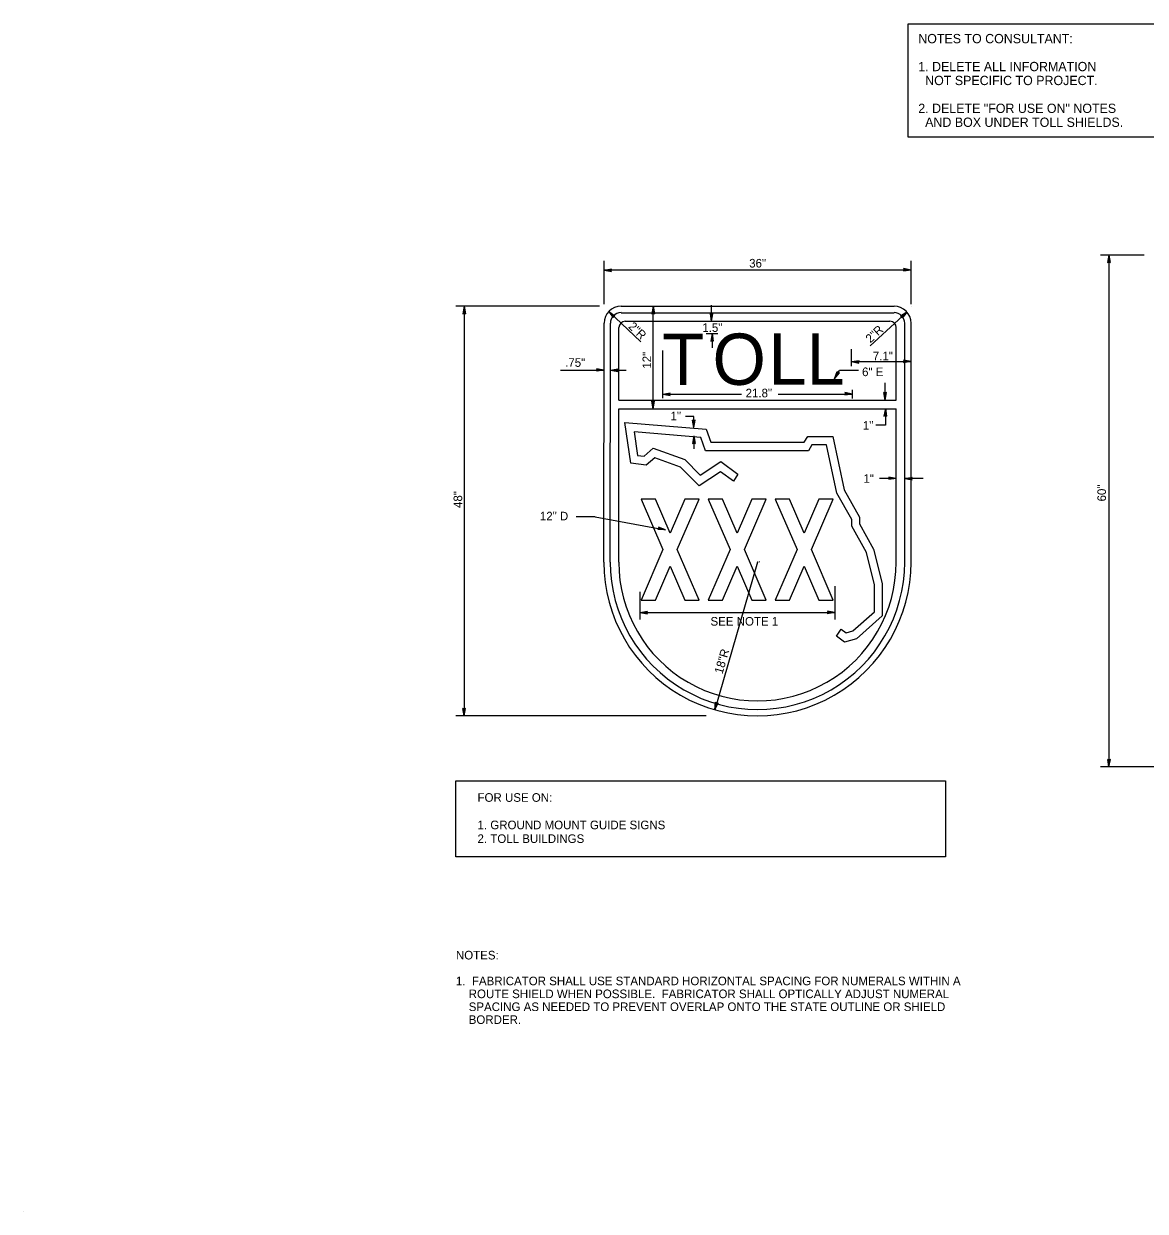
# Model space of a CAD drawing. Extents: x 52194 to 54069, y 8993 to 10153.
# Drawn here: x 52194 to 53290, y 8993 to 10153 of the extents above; entities that cross this region are included whole.
import ezdxf

# ---------------------------------------------------------------- set-up
doc = ezdxf.new("R2010")
doc.units = 0
for name, color, linetype in [('AdhocPoint_dp', 7, 'Continuous'), ('GSDims', 7, 'Continuous'), ('SignPanel', 7, 'Continuous'), ('TextAlert', 7, 'Continuous'), ('TextLabel', 7, 'Continuous'), ('TextNotes', 7, 'Continuous')]:
    doc.layers.add(name, color=color, linetype=linetype)

msp = doc.modelspace()

# ---------------------------------------------------------------- linework, layer by layer
at = {"layer": 'AdhocPoint_dp'}
msp.add_line((52193.9, 8993), (52193.9, 8993), dxfattribs=at)
at = {"layer": 'GSDims'}
for p, q in [((52760.8, 9879), (52760.8, 9921.6)), ((53060.8, 9879), (53060.8, 9921.6)), ((53288.6, 9927), (53246, 9927)), ((53254.1, 9927), (53252.7, 9919.8)), ((53252.7, 9919.8), (53254, 9920.3)), ((53254.1, 9927), (53253.3, 9920)), ((53254, 9920.3), (53255.2, 9919.7)), ((53254.1, 9927), (53255.2, 9919.7)), ((53254.1, 9927), (53254.6, 9920)), ((53254.1, 9927), (53254.1, 9427)), ((52760.8, 9912.4), (52768.1, 9913.5)), ((52760.8, 9912.4), (52767.8, 9912.9)), ((52760.8, 9912.4), (52768.1, 9911)), ((52760.8, 9912.4), (52767.8, 9911.6)), ((53060.8, 9912.4), (52760.8, 9912.4)), ((52767.6, 9912.3), (52768.1, 9913.5)), ((52768.1, 9911), (52767.6, 9912.3)), ((53060.8, 9912.4), (53053.5, 9913.8)), ((53053.5, 9913.8), (53054, 9912.5)), ((53054, 9912.5), (53053.5, 9911.2)), ((53060.8, 9912.4), (53053.5, 9911.2)), ((53060.8, 9912.4), (53053.8, 9913.1)), ((53060.8, 9912.4), (53053.8, 9911.9)), ((52756.4, 9877), (52616.1, 9877)), ((52624.2, 9877), (52622.8, 9869.7)), ((52624.2, 9877), (52623.4, 9870)), ((52624.2, 9877), (52625.3, 9869.7)), ((52624.2, 9877), (52624.7, 9870)), ((52624.2, 9877), (52624.2, 9477)), ((52660.7, 9877), (52660.7, 9877)), ((52765.4, 9871.9), (52796.7, 9842.4)), ((52765.4, 9871.9), (52771.5, 9867.7)), ((52765.4, 9871.9), (52769.7, 9865.9)), ((52765.4, 9871.9), (52770, 9866.6)), ((52765.4, 9871.9), (52770.9, 9867.4)), ((52808.8, 9877), (52807.4, 9869.7)), ((52808.8, 9877), (52808.1, 9870)), ((52808.8, 9877), (52810, 9869.7)), ((52808.8, 9877), (52809.3, 9870)), ((52808.8, 9777), (52808.8, 9877)), ((52865.8, 9862.4), (52865.8, 9878.1)), ((53060.8, 9877), (53060.8, 9877)), ((52622.8, 9869.7), (52624.1, 9870.2)), ((52624.1, 9870.2), (52625.3, 9869.7)), ((52769.7, 9865.9), (52770.2, 9867.2)), ((52770.2, 9867.2), (52771.5, 9867.7)), ((52807.4, 9869.7), (52808.7, 9870.3)), ((52808.7, 9870.3), (52810, 9869.7)), ((52865.8, 9862.4), (52864.7, 9869.7)), ((52865.9, 9869.2), (52864.7, 9869.7)), ((52865.8, 9862.4), (52865.3, 9869.4)), ((52865.8, 9862.4), (52867.2, 9869.7)), ((52865.8, 9862.4), (52866.6, 9869.4)), ((52867.2, 9869.7), (52865.9, 9869.2)), ((53056.7, 9871.3), (53020.9, 9838.3)), ((53056.7, 9871.3), (53050.4, 9867.4)), ((53050.4, 9867.4), (53051.6, 9866.8)), ((53056.7, 9871.3), (53051, 9867.1)), ((53051.6, 9866.8), (53052.1, 9865.5)), ((53056.7, 9871.3), (53051.9, 9866.2)), ((53056.7, 9871.3), (53052.1, 9865.5)), ((52860.7, 9850.4), (52872.1, 9850.4)), ((52866.4, 9850.4), (52865, 9843.1)), ((52866.4, 9850.4), (52865.6, 9843.4)), ((52866.4, 9850.4), (52866.4, 9836.4)), ((52866.4, 9850.4), (52867.5, 9843.1)), ((52866.4, 9850.4), (52866.9, 9843.4)), ((52865, 9843.1), (52866.3, 9843.6)), ((52866.3, 9843.6), (52867.5, 9843.1)), ((53026.4, 9842.4), (53026.4, 9842.4)), ((52818.1, 9787.2), (52818.1, 9834)), ((53002.6, 9818.5), (53002.6, 9835)), ((52718.4, 9814.7), (52760.8, 9814.7)), ((52760.8, 9814.7), (52753.5, 9816.1)), ((52753.5, 9816.1), (52754, 9814.8)), ((52754, 9814.8), (52753.5, 9813.6)), ((52760.8, 9814.7), (52753.5, 9813.6)), ((52760.8, 9814.7), (52753.8, 9815.5)), ((52760.8, 9814.7), (52753.8, 9814.2)), ((52767, 9814.7), (52774.3, 9815.9)), ((52767, 9814.7), (52774, 9815.2)), ((52767, 9814.7), (52774.2, 9813.3)), ((52767, 9814.7), (52774, 9814)), ((52767, 9814.7), (52782.3, 9814.7)), ((52773.7, 9814.6), (52774.3, 9815.9)), ((52774.2, 9813.3), (52773.7, 9814.6)), ((52986, 9806.3), (52990.7, 9814.4)), ((53009.4, 9814.4), (52990.7, 9814.4)), ((53002.6, 9823), (53009.9, 9824.2)), ((53002.6, 9823), (53009.6, 9823.5)), ((53002.6, 9823), (53060.8, 9823)), ((53002.6, 9823), (53009.8, 9821.6)), ((53002.6, 9823), (53009.6, 9822.3)), ((53009.3, 9822.9), (53009.9, 9824.2)), ((53009.8, 9821.6), (53009.3, 9822.9)), ((53060.8, 9823), (53053.5, 9824.4)), ((53053.5, 9824.4), (53054, 9823.1)), ((53054, 9823.1), (53053.5, 9821.9)), ((53060.8, 9823), (53053.5, 9821.9)), ((53060.8, 9823), (53053.8, 9823.8)), ((53060.8, 9823), (53053.8, 9822.5)), ((52986, 9806.3), (52988.6, 9813.2)), ((52986, 9806.3), (52989.1, 9812.6)), ((52986, 9806.3), (52990.1, 9812)), ((52986, 9806.3), (52990.9, 9811.9)), ((52989.5, 9812.1), (52988.6, 9813.2)), ((52990.9, 9811.9), (52989.5, 9812.1)), ((53035.6, 9785.4), (53035.4, 9802.3)), ((52818.1, 9791.3), (52825.4, 9792.5)), ((52818.1, 9791.3), (52825.1, 9791.8)), ((52818.1, 9791.3), (52825.4, 9789.9)), ((52818.1, 9791.3), (52825.1, 9790.6)), ((52818.1, 9791.3), (52895.2, 9791.3)), ((52824.8, 9791.2), (52825.4, 9792.5)), ((52825.4, 9789.9), (52824.8, 9791.2)), ((52931, 9791.3), (53003.5, 9791.3)), ((53003.5, 9791.3), (52996.2, 9792.7)), ((52996.2, 9792.7), (52996.8, 9791.4)), ((52996.8, 9791.4), (52996.2, 9790.1)), ((53003.5, 9791.3), (52996.2, 9790.1)), ((53003.5, 9791.3), (52996.5, 9792)), ((53003.5, 9791.3), (52996.5, 9790.8)), ((53003.5, 9787), (53003.5, 9795.5)), ((53035.6, 9785.4), (53034.3, 9792.7)), ((53035.6, 9792.1), (53034.3, 9792.7)), ((53035.6, 9785.4), (53035, 9792.4)), ((53035.6, 9785.4), (53036.9, 9792.7)), ((53036.9, 9792.7), (53035.6, 9792.1)), ((53035.6, 9785.4), (53036.2, 9792.4)), ((52808.8, 9777), (52807.6, 9784.3)), ((52808.9, 9783.7), (52807.6, 9784.3)), ((52808.8, 9777), (52808.3, 9784)), ((52808.8, 9777), (52810.2, 9784.3)), ((52808.8, 9777), (52809.5, 9784)), ((52810.2, 9784.3), (52808.9, 9783.7)), ((52848.4, 9769.3), (52840.5, 9769.3)), ((52848.4, 9758.6), (52848.4, 9769.3)), ((53035.7, 9777.1), (53034.3, 9769.8)), ((53034.3, 9769.8), (53035.6, 9770.3)), ((53035.7, 9777.1), (53035, 9770.1)), ((53035.6, 9770.3), (53036.9, 9769.8)), ((53035.7, 9777.1), (53035.9, 9761)), ((53035.7, 9777.1), (53036.9, 9769.8)), ((53035.7, 9777.1), (53036.2, 9770.1)), ((52848.4, 9758.6), (52847.2, 9765.9)), ((52848.5, 9765.3), (52847.2, 9765.9)), ((52848.4, 9758.6), (52847.9, 9765.6)), ((52848.4, 9758.6), (52849.8, 9765.9)), ((52848.4, 9758.6), (52849.1, 9765.6)), ((52849.8, 9765.9), (52848.5, 9765.3)), ((53035.9, 9761), (53026.2, 9761)), ((52848.4, 9750.4), (52847.1, 9743.1)), ((52848.4, 9750.4), (52847.8, 9743.4)), ((52848.4, 9750.4), (52848.6, 9737.9)), ((52848.4, 9750.4), (52849.7, 9743.1)), ((52848.4, 9750.4), (52849, 9743.4)), ((52847.1, 9743.1), (52848.4, 9743.7)), ((52848.4, 9743.7), (52849.7, 9743.1)), ((53046.3, 9708.8), (53039, 9710.2)), ((53039, 9710.2), (53039.5, 9708.9)), ((53046.3, 9708.8), (53039.3, 9709.6)), ((53054.6, 9708.8), (53061.9, 9710)), ((53054.6, 9708.8), (53061.6, 9709.3)), ((53061.3, 9708.7), (53061.9, 9710)), ((53046.3, 9708.8), (53029.8, 9708.8)), ((53039.5, 9708.9), (53039, 9707.7)), ((53046.3, 9708.8), (53039, 9707.7)), ((53046.3, 9708.8), (53039.3, 9708.3)), ((53054.6, 9708.8), (53061.8, 9707.4)), ((53054.6, 9708.8), (53061.6, 9708.1)), ((53072.5, 9708.8), (53054.6, 9708.8)), ((53061.8, 9707.4), (53061.3, 9708.7)), ((52752.1, 9671.4), (52733.7, 9671.4)), ((52752.1, 9671.4), (52820.9, 9658.7)), ((52814.3, 9660.1), (52813.5, 9658.9)), ((52820.9, 9658.7), (52813.5, 9658.9)), ((52820.9, 9658.7), (52814, 9661.4)), ((52814, 9661.4), (52814.3, 9660.1)), ((52820.9, 9658.7), (52814, 9659.5)), ((52820.9, 9658.7), (52814.2, 9660.7)), ((52910.8, 9627), (52869.2, 9482.9)), ((52910.8, 9627), (52910.8, 9627)), ((52910.8, 9627), (52910.8, 9627)), ((52795.9, 9598), (52795.9, 9571)), ((52986.3, 9603.8), (52986.3, 9571)), ((52795.9, 9577.9), (52803.2, 9579.1)), ((52795.9, 9577.9), (52802.9, 9578.4)), ((52795.9, 9577.9), (52803.2, 9576.5)), ((52795.9, 9577.9), (52802.9, 9577.2)), ((52795.9, 9577.9), (52875.5, 9577.9)), ((52802.6, 9577.8), (52803.2, 9579.1)), ((52803.2, 9576.5), (52802.6, 9577.8)), ((52875.5, 9577.9), (52986.3, 9577.9)), ((52986.3, 9577.9), (52979, 9579.3)), ((52979, 9579.3), (52979.6, 9578)), ((52979.6, 9578), (52979, 9576.7)), ((52986.3, 9577.9), (52979, 9576.7)), ((52986.3, 9577.9), (52979.3, 9578.6)), ((52986.3, 9577.9), (52979.3, 9577.4)), ((52869.2, 9482.9), (52869.8, 9490.3)), ((52869.2, 9482.9), (52870.4, 9489.9)), ((52869.2, 9482.9), (52872.3, 9489.6)), ((52869.2, 9482.9), (52871.6, 9489.5)), ((52869.8, 9490.3), (52871, 9489.4)), ((52871, 9489.4), (52872.3, 9489.6)), ((52624.2, 9477), (52623, 9484.3)), ((52624.3, 9483.7), (52623, 9484.3)), ((52624.2, 9477), (52623.7, 9484)), ((52624.2, 9477), (52625.6, 9484.3)), ((52624.2, 9477), (52624.9, 9484)), ((52625.6, 9484.3), (52624.3, 9483.7)), ((52860.6, 9477), (52616.1, 9477)), ((53254.1, 9427), (53252.9, 9434.3)), ((53254.2, 9433.8), (53252.9, 9434.3)), ((53254.1, 9427), (53253.6, 9434)), ((53254.1, 9427), (53255.5, 9434.3)), ((53254.1, 9427), (53254.8, 9434)), ((53255.5, 9434.3), (53254.2, 9433.8)), ((53490.5, 9427), (53246, 9427))]:
    msp.add_line(p, q, dxfattribs=at)
for radius in [0.141, 0.141, 0.0707]:
    msp.add_circle((52910.8, 9627.1), radius, dxfattribs=at)
at = {"layer": 'SignPanel'}
for p, q in [((52777.4, 9877), (53044.1, 9877)), ((52760.7, 9627.1), (52760.8, 9860.4)), ((52766.9, 9627.1), (52767, 9860.4)), ((52777.4, 9870.7), (53044.1, 9870.7)), ((52781.5, 9862.4), (53040.1, 9862.4)), ((53054.6, 9627), (53054.6, 9860.4)), ((53060.8, 9627), (53060.8, 9860.4)), ((52775.3, 9785.3), (52775.3, 9856.2)), ((53046.3, 9785.3), (53046.3, 9856.2)), ((52775.3, 9785.3), (53046.3, 9785.3)), ((52775.3, 9627), (52775.3, 9777)), ((52775.3, 9777), (53046.3, 9777)), ((53046.3, 9627), (53046.3, 9777)), ((52781.2, 9763.6), (52860.7, 9756.9)), ((52786.9, 9723.9), (52781.2, 9763.6)), ((52860.7, 9756.9), (52865.2, 9744.4)), ((52855.3, 9749), (52790.3, 9754.4)), ((52790.3, 9754.4), (52793.6, 9731.4)), ((52859.9, 9736), (52855.3, 9749)), ((52865.2, 9744.4), (52956.3, 9744.4)), ((52956.3, 9744.4), (52959.8, 9750)), ((52959.8, 9750), (52984.3, 9750)), ((52984.3, 9750), (52995.4, 9697.7)), ((52799.9, 9730.6), (52808.9, 9738.3)), ((52808.9, 9738.3), (52839.6, 9727.4)), ((52960.4, 9736), (52859.9, 9736)), ((52963.9, 9741.6), (52960.4, 9736)), ((52978.2, 9741.6), (52963.9, 9741.6)), ((52988.2, 9694.5), (52978.2, 9741.6)), ((52802.1, 9721.8), (52786.9, 9723.9)), ((52793.6, 9731.4), (52799.9, 9730.6)), ((52810.4, 9729), (52802.1, 9721.8)), ((52835.6, 9720), (52810.4, 9729)), ((52839.6, 9727.4), (52854.6, 9712.2)), ((52854.6, 9712.2), (52875, 9725.3)), ((52875, 9725.3), (52891.6, 9713)), ((52853.6, 9701.8), (52835.6, 9720)), ((52874.7, 9715.4), (52853.6, 9701.8)), ((52887.3, 9706.1), (52874.7, 9715.4)), ((52891.6, 9713), (52887.3, 9706.1)), ((52995.4, 9697.7), (53010.5, 9671.2)), ((52811.1, 9688.5), (52797.1, 9688.5)), ((52797.1, 9688.5), (52818.4, 9639.3)), ((52825.4, 9655.4), (52811.1, 9688.5)), ((52839.8, 9688.5), (52825.4, 9655.4)), ((52832.4, 9639.3), (52853.8, 9688.5)), ((52853.8, 9688.5), (52839.8, 9688.5)), ((52876.6, 9688.5), (52862.6, 9688.5)), ((52862.6, 9688.5), (52883.9, 9639.3)), ((52890.9, 9655.4), (52876.6, 9688.5)), ((52905.3, 9688.5), (52890.9, 9655.4)), ((52897.9, 9639.3), (52919.3, 9688.5)), ((52919.3, 9688.5), (52905.3, 9688.5)), ((52942.1, 9688.5), (52928.1, 9688.5)), ((52928.1, 9688.5), (52949.4, 9639.3)), ((52956.4, 9655.4), (52942.1, 9688.5)), ((52970.8, 9688.5), (52956.4, 9655.4)), ((52963.4, 9639.3), (52984.8, 9688.5)), ((52984.8, 9688.5), (52970.8, 9688.5)), ((53002.9, 9668.8), (52988.2, 9694.5)), ((53002.9, 9662.1), (53002.9, 9668.8)), ((53010.5, 9671.2), (53010.5, 9664.4)), ((53010.5, 9664.4), (53024.2, 9639.8)), ((53017.1, 9636.5), (53002.9, 9662.1)), ((53024.2, 9639.8), (53032.6, 9606.1)), ((52818.4, 9639.3), (52797.1, 9590.1)), ((52853.8, 9590.1), (52832.4, 9639.3)), ((52883.9, 9639.3), (52862.6, 9590.1)), ((52919.3, 9590.1), (52897.9, 9639.3)), ((52949.4, 9639.3), (52928.1, 9590.1)), ((52984.8, 9590.1), (52963.4, 9639.3)), ((53025, 9605), (53017.1, 9636.5)), ((52811.1, 9590.1), (52825.4, 9623.2)), ((52825.4, 9623.2), (52839.8, 9590.1)), ((52876.6, 9590.1), (52890.9, 9623.2)), ((52890.9, 9623.2), (52905.3, 9590.1)), ((52942.1, 9590.1), (52956.4, 9623.2)), ((52956.4, 9623.2), (52970.8, 9590.1)), ((53025, 9578.6), (53025, 9605)), ((53032.6, 9606.1), (53032.6, 9574.7)), ((52797.1, 9590.1), (52811.1, 9590.1)), ((52839.8, 9590.1), (52853.8, 9590.1)), ((52862.6, 9590.1), (52876.6, 9590.1)), ((52905.3, 9590.1), (52919.3, 9590.1)), ((52928.1, 9590.1), (52942.1, 9590.1)), ((52970.8, 9590.1), (52984.8, 9590.1)), ((53004, 9559.9), (53025, 9578.6)), ((53032.6, 9574.7), (53007.5, 9552.1)), ((52988, 9554.8), (52992.4, 9561.6)), ((52992.4, 9561.6), (52997.2, 9558.1)), ((52997.2, 9558.1), (53004, 9559.9)), ((52995.6, 9549), (52988, 9554.8)), ((53007.5, 9552.1), (52995.6, 9549))]:
    msp.add_line(p, q, dxfattribs=at)
for centre, radius, start, end in [((52777.5, 9860.4), 16.7, 90, 179.9763), ((53044.1, 9860.4), 16.7, 0, 90), ((52777.5, 9860.4), 10.5, 90, 179.9763), ((52781.5, 9856.2), 6.2, 90, 180), ((53040.1, 9856.2), 6.2, 0, 90), ((53044.1, 9860.4), 10.5, 0, 90), ((52910.7, 9627.1), 150.1, 179.9809, 359.9809), ((52910.7, 9627.1), 143.9, 179.9809, 359.9809), ((52910.7, 9627.1), 135.5, 179.9809, 359.9809)]:
    msp.add_arc(centre, radius, start, end, dxfattribs=at)
at = {"layer": 'TextAlert'}
msp.add_lwpolyline([(53057.8, 10153), (53309.9, 10153), (53309.9, 10042.3), (53057.8, 10042.3)], close=True, dxfattribs=at)
at = {"layer": 'TextLabel'}
msp.add_lwpolyline([(52616.1, 9413.6), (53094.4, 9413.6), (53094.4, 9339.3), (52616.1, 9339.3)], close=True, dxfattribs=at)

# ---------------------------------------------------------------- texts
at = {"layer": 'GSDims'}
for s, p in [('36"', (52902.6, 9914.9)), ('1.5"', (52856.8, 9852)), ('.75"', (52722.8, 9817.9)), ('7.1"', (53023.4, 9824.3)), ('6" E', (53012.9, 9808.8)), ('21.8"', (52899.1, 9788.1)), ('1"', (52825.8, 9765.7)), ('1"', (53013.7, 9756.5)), ('1"', (53014.2, 9704.6)), ('12" D', (52698.1, 9667.9)), ('SEE NOTE 1', (52864.8, 9565.1))]:
    msp.add_text(s, height=8.4, dxfattribs=at).set_placement(p)
for s, rotation, p in [('2"R', 316.5174, (52783.9, 9856.5)), ('2"R', 42.5752, (53021, 9840.7)), ('12"', 90, (52806.8, 9816.1)), ('60"', 90, (53251.2, 9686.4)), ('48"', 90, (52622.2, 9680)), ('.', 90, (52913.3, 9625.9)), ('18"R', 73.8557, (52876.5, 9517.3))]:
    msp.add_text(s, height=8.4, rotation=rotation, dxfattribs=at).set_placement(p)
at = {"layer": 'SignPanel'}
for s, height, p in [('T', 50.1, (52817.7, 9800.2)), ('O', 50.1, (52866.8, 9800.3)), ('LL', 50.08, (52921.5, 9800.5))]:
    msp.add_text(s, height=height, dxfattribs=at).set_placement(p)
at = {"layer": 'TextAlert'}
for s, p in [('NOTES TO CONSULTANT:', (53067.8, 10134)), ('1. DELETE ALL INFORMATION', (53067.8, 10106.7)), ('  NOT SPECIFIC TO PROJECT.', (53067.8, 10093.1)), ('2. DELETE "FOR USE ON" NOTES', (53067.8, 10065.9)), ('  AND BOX UNDER TOLL SHIELDS.', (53067.8, 10052.3))]:
    msp.add_text(s, height=9.072, dxfattribs=at).set_placement(p)
at = {"layer": 'TextLabel'}
for s, p in [('FOR USE ON:', (52637.2, 9393)), ('1. GROUND MOUNT GUIDE SIGNS', (52637.2, 9366.2)), ('2. TOLL BUILDINGS', (52637.2, 9352.8))]:
    msp.add_text(s, height=8.4, dxfattribs=at).set_placement(p)
at = {"layer": 'TextNotes'}
for s, p in [('NOTES:', (52616.1, 9239)), ('1.  FABRICATOR SHALL USE STANDARD HORIZONTAL SPACING FOR NUMERALS WITHIN A', (52616.1, 9213.8)), ('    ROUTE SHIELD WHEN POSSIBLE.  FABRICATOR SHALL OPTICALLY ADJUST NUMERAL', (52616.1, 9201.2)), ('    SPACING AS NEEDED TO PREVENT OVERLAP ONTO THE STATE OUTLINE OR SHIELD ', (52616.1, 9188.6)), ('    BORDER.', (52616.1, 9176))]:
    msp.add_text(s, height=8.4, dxfattribs=at).set_placement(p)

doc.saveas('drawing.dxf')
